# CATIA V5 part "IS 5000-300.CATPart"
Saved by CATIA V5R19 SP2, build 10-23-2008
Part number: IS 5000-300
Bounding box of the stored display mesh (mm): x -59.975 to 59.975, y -59.975 to 59.975, z 0 to 740
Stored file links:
  C:\Users\Bora\Desktop\3D Katı model\IS serisi\IS 5000\IS 5000-300.CATPart
  C:\Program Files\Dassault Systemes\B19\intel_a\reffiles\standard\MetricThickPitch.txt
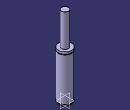
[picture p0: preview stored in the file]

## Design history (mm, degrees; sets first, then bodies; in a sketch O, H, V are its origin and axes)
Body1 (main body)
  Sketch1 on yz-plane, origin (0, 0, 0), H (0, 1, 0), V (0, 0, 1)
    point P1 (60, 417)
    point P4 (60, 412)
    point P7 (32.5, 739)
    point P9 (32.5, 739)
    point P13 (60, 417)
    point P14 (60, 412)
    line L1 (60, 417) -> (60, 437)
    line L2 (60, 13) -> (60, 412)
    line L3 (56, 13) -> (56, 8)
    arc A1 centre (31.5, 739) radius 1 from (32.5, 739) to (31.5, 740) ccw
    line L4 (32.5, 739) -> (32.5, 437)
    line L5 (60, 0) -> (60, 8)
    arc A2 centre (60, 414.5) radius 2.5 from (60, 417) to (60, 412) ccw
    line L6 (0, 0) -> (60, 0)
    line L7 (31.5, 740) -> (0, 740)
    point P15 (0, 740)
    line L8 (32.5, 437) -> (60, 437)
    line L9 (56, 13) -> (60, 13)
    line L10 (56, 8) -> (60, 8)
    horizontal: L6 H, L8 H, L9 H, L10 H
    coincidence: P15 V, P1 P13, P4 P14, P7 P9
    tangency: L7 A1
  Shaft1: profile Sketch1, axis Sketch1.V, angle 360
  Sketch2 on face of Shaft1 from Sketch1.L6, origin (0, 0, 0), H (1, 0, 0), V (0, -1, 0)
    point P1 (40, 0)
    distance P1 V = 40
  Hole1: placed by Sketch2, at (40, 0, 0) direction (0, 0, 1), diameter 8.376, depth 16, threaded "M10", thread diameter 10, thread depth 16, pitch 1.5
  CircPattern1: of Hole1, instances 4, angular step 90, axis from xy-plane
